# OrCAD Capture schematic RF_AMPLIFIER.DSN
size A
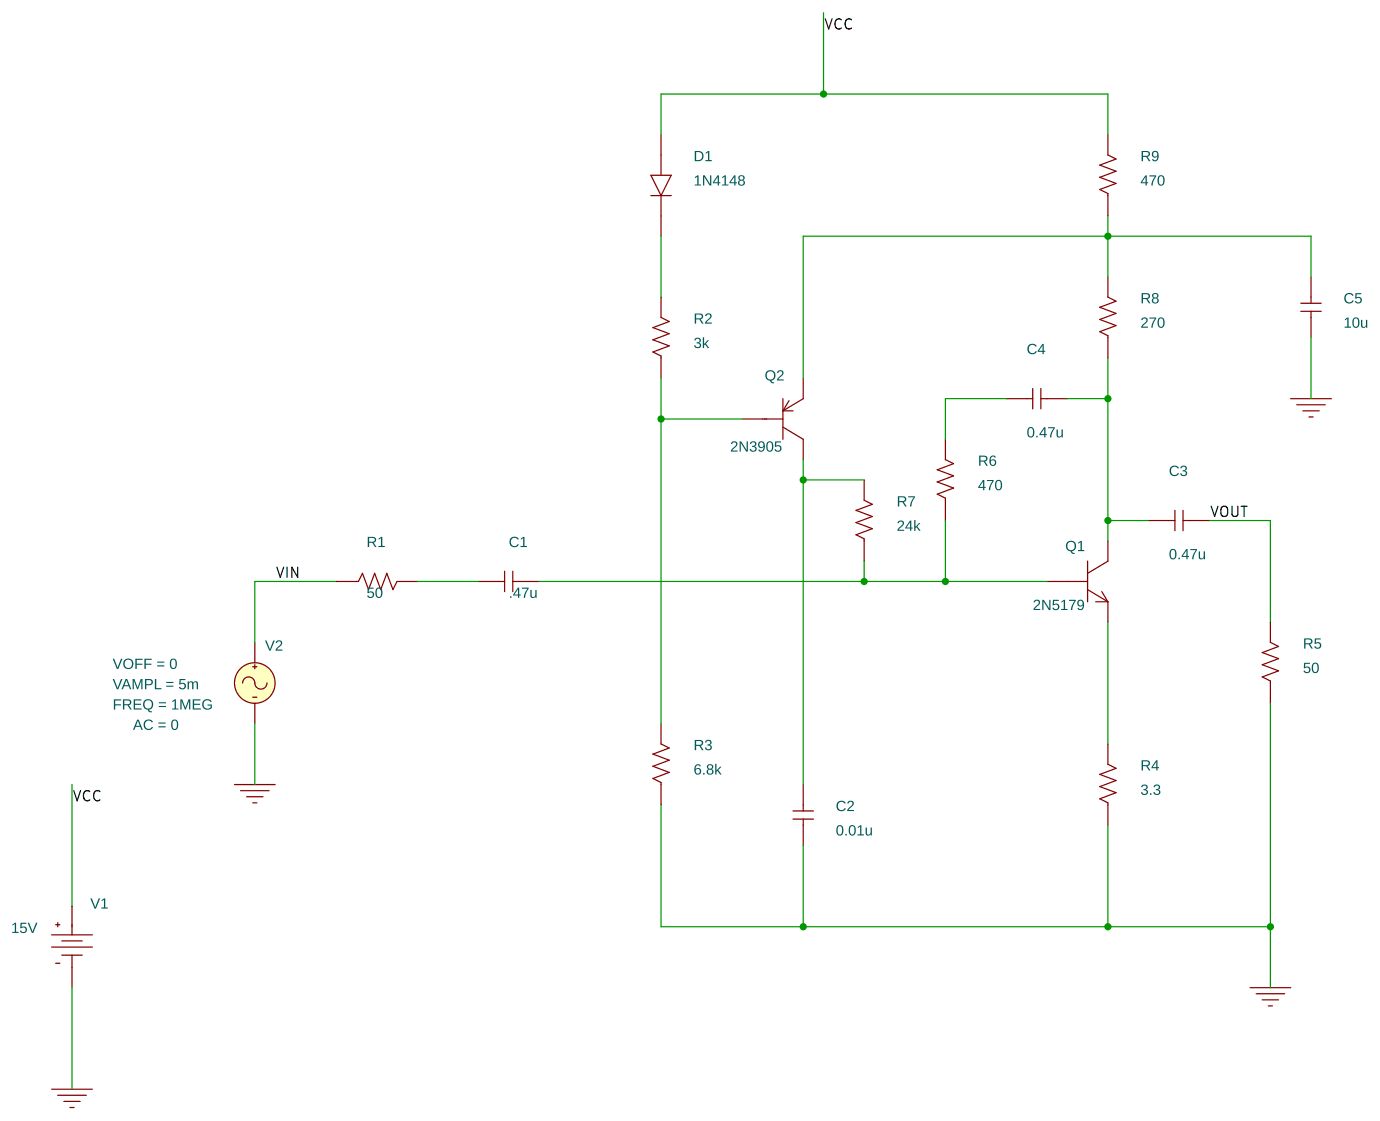
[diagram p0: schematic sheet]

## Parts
C1  .47u  [cap196]
C2  0.01u  [cap196]
C3  0.47u  [cap196]
C4  0.47u  [cap196]
C5  10u  [cap196]
D1  1N4148  [dax2do35]
Q1  2N5179  [TO72]
Q2  2N3905  [TO92]
R1  50  [AXRC05]
R2  3k  [AXRC05]
R3  6.8k  [AXRC05]
R4  3.3  [AXRC05]
R5  50  [AXRC05]
R6  470  [AXRC05]
R7  24k  [AXRC05]
R8  270  [AXRC05]
R9  470  [AXRC05]
V1  VDC
V2  VSIN

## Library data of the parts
C1-C5 = C
D1 = 1N4148
Q1 = 2N5179
Q2 = 2N3905
R1-R9 = R
V1 = VDC: DC: 15V
V2 = VSIN: AC: 0; FREQ: 1MEG; VAMPL: 5m; VOFF: 0

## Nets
VCC: D1.2(AN) R9.2 V1.0(+)
VIN: R1.1 V2.1(+)
0: C2.1 C5.1 R3.1 R4.1 R5.1 V1.1(-) V2.2(-)
VOUT: C3.1 R5.2
N00249: C1.1 R1.2
N00349: D1.1(CAT) R2.2
N00388: Q2.2(B) R2.1 R3.2
N00539: C1.2 Q1.2(B) R6.1 R7.1
N00547: Q1.1(E) R4.2
N00589: C3.2 C4.1 Q1.3(C) R8.1
N00817: C4.2 R6.2
N00862: C2.2 Q2.3(C) R7.2
N01082: C5.2 Q2.1(E) R8.2 R9.1
